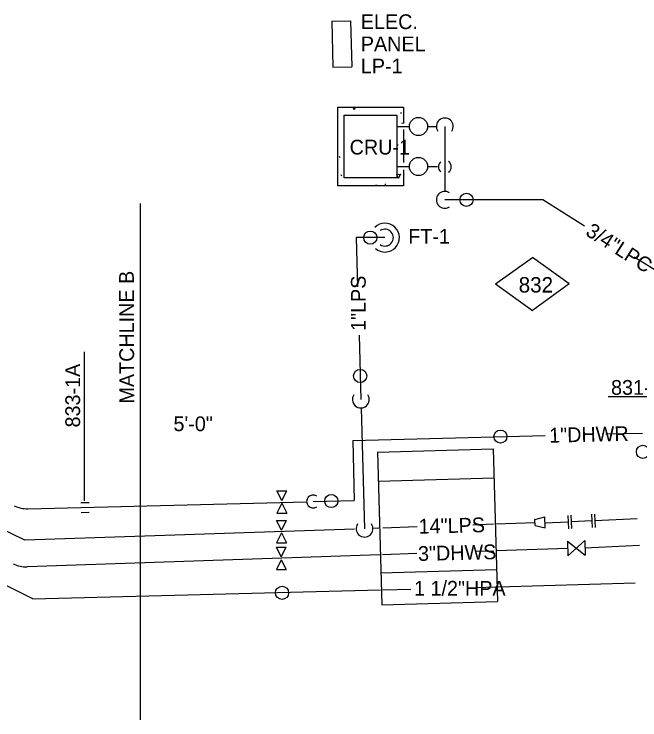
# Model space of a CAD drawing. Extents: x 9888 to 10178, y 10284 to 10314.
# Drawn here: x 9928.84 to 9944.72, y 10285.52 to 10303.43 of the extents above; entities that cross this region are included whole.
import ezdxf

# ---------------------------------------------------------------- set-up
doc = ezdxf.new("R2010")
doc.units = 0
for name, color, linetype in [('Level 51', 7, 'Continuous'), ('Level 52', 7, 'Continuous'), ('Level 55', 7, 'Continuous'), ('Level 62', 7, 'Continuous'), ('M-ANNO-NPLT', 7, 'Continuous'), ('M-EQPM-N', 7, 'Continuous'), ('M-HVAC-SUPP-N', 7, 'Continuous'), ('M-PROC-PIPE', 7, 'Continuous'), ('M-STEM-CONP', 7, 'Continuous'), ('M-STEM-CONP-N', 7, 'Continuous'), ('P-CMPA-PIPE', 7, 'Continuous'), ('P-DOMW-HPIP', 7, 'Continuous'), ('P-DOMW-HPIP-N', 7, 'Continuous')]:
    doc.layers.add(name, color=color, linetype=linetype)

msp = doc.modelspace()

# ---------------------------------------------------------------- linework, layer by layer
at = {"layer": 'Level 51'}
for p, q in [((9938.669, 10300.9), (9938.656, 10300.934)), ((9938.556, 10300.581), (9938.869, 10300.581)), ((9938.666, 10300.673), (9938.692, 10300.668)), ((9939.331, 10300.581), (9939.547, 10300.581)), ((9939.768, 10300.581), (9939.768, 10298.937)), ((9937.113, 10299.788), (9937.1, 10299.822)), ((9938.556, 10299.564), (9938.869, 10299.564)), ((9939.331, 10299.564), (9939.586, 10299.564)), ((9937.155, 10299.322), (9937.142, 10299.356)), ((9938.245, 10299.126), (9938.271, 10299.105)), ((9942.258, 10298.719), (9939.768, 10298.719)), ((9943.318, 10298.054), (9942.258, 10298.719)), ((9938.249, 10297.759), (9937.521, 10297.759)), ((9937.521, 10297.759), (9937.556, 10296.514)), ((9941.058, 10296.583), (9941.991, 10297.255)), ((9942.924, 10296.583), (9941.991, 10297.255)), ((9945.996, 10296.374), (9944.576, 10297.265)), ((9941.058, 10296.583), (9941.991, 10295.911)), ((9942.924, 10296.583), (9941.991, 10295.911)), ((9937.592, 10295.279), (9937.638, 10293.651)), ((9937.644, 10293.437), (9937.732, 10290.37)), ((9938.058, 10292.312), (9940.999, 10292.396)), ((9938.058, 10292.312), (9938.169, 10288.439)), ((9940.999, 10292.396), (9941.11, 10288.523)), ((9938.079, 10291.573), (9941.02, 10291.657)), ((9938.146, 10289.246), (9941.087, 10289.33)), ((9938.169, 10288.439), (9941.11, 10288.523))]:
    msp.add_line(p, q, dxfattribs=at)
for points in [[(9938.721, 10299.48), (9938.721, 10299.072), (9937.054, 10299.072), (9937.054, 10301.072), (9938.721, 10301.072), (9938.721, 10300.656)], [(9937.469, 10301.004), (9937.445, 10301.072)], [(9937.504, 10301.072), (9937.469, 10301.004)], [(9938.721, 10300.506), (9938.721, 10299.663)], [(9938.549, 10300.119), (9938.574, 10300.123), (9938.549, 10300.075)], [(9938.585, 10299.263), (9938.551, 10299.359), (9938.643, 10299.372), (9938.585, 10299.263)], [(9938.026, 10299.072), (9938.01, 10299.093), (9938.05, 10299.092)]]:
    msp.add_lwpolyline(points, dxfattribs=at)
msp.add_lwpolyline([(9937.215, 10299.28), (9937.215, 10300.864), (9938.549, 10300.864), (9938.549, 10299.28)], close=True, dxfattribs=at)
for centre, radius in [((9939.1, 10300.581), 0.231), ((9939.1, 10299.564), 0.231), ((9940.32, 10298.719), 0.167), ((9937.878, 10297.759), 0.167), ((9937.621, 10294.247), 0.167)]:
    msp.add_circle(centre, radius, dxfattribs=at)
for centre, radius, start, end in [((9939.768, 10300.581), 0.214, 326.0383, 213.8362), ((9939.769, 10299.555), 0.164, 127.3529, 230.1974), ((9939.769, 10299.555), 0.164, 304.8908, 55.1092), ((9939.768, 10298.719), 0.214, 56.0383, 303.8362), ((9938.249, 10297.759), 0.366, 228.3299, 134.4653), ((9938.249, 10297.759), 0.214, 236.0383, 123.8362), ((9937.638, 10293.651), 0.214, 146.0383, 33.8362), ((9937.732, 10290.37), 0.214, 146.0383, 33.8362)]:
    msp.add_arc(centre, radius, start, end, dxfattribs=at)
at = {"layer": 'Level 55'}
for centre in [(9941.18, 10292.708), (9944.798, 10292.32), (9936.888, 10291.072)]:
    msp.add_circle(centre, 0.167, dxfattribs=at)
at = {"layer": 'Level 62'}
for p, q in [((9936.902, 10303.254), (9937.378, 10303.265)), ((9936.902, 10303.254), (9936.928, 10302.088)), ((9937.378, 10303.265), (9937.405, 10302.098)), ((9936.928, 10302.088), (9937.405, 10302.098))]:
    msp.add_line(p, q, dxfattribs=at)
at = {"layer": 'M-ANNO-NPLT'}
msp.add_line((9930.627, 10291.078), (9930.627, 10294.861), dxfattribs=at)
at = {"layer": 'M-EQPM-N'}
msp.add_line((9945.961, 10293.714), (9943.913, 10293.714), dxfattribs=at)
at = {"layer": 'M-PROC-PIPE'}
for p, q in [((9937.433, 10292.612), (9942.315, 10292.737)), ((9943.856, 10292.776), (9944.79, 10292.799)), ((9937.433, 10292.612), (9937.471, 10291.086)), ((9935.631, 10291.084), (9935.507, 10291.332)), ((9935.507, 10291.332), (9935.755, 10291.332)), ((9935.631, 10291.084), (9935.755, 10291.332)), ((9929.186, 10290.876), (9936.261, 10291.056)), ((9936.425, 10291.06), (9937.471, 10291.086)), ((9930.534, 10291.033), (9930.738, 10291.038)), ((9935.631, 10291.015), (9935.507, 10290.767)), ((9935.631, 10291.015), (9935.755, 10290.767)), ((9930.54, 10290.783), (9930.744, 10290.788)), ((9935.507, 10290.767), (9935.755, 10290.767))]:
    msp.add_line(p, q, dxfattribs=at)
for centre, radius, start, end in [((9936.425, 10291.06), 0.164, 56.0383, 303.8362), ((9929.167, 10291.626), 0.75, 243.8756, 271.4564)]:
    msp.add_arc(centre, radius, start, end, dxfattribs=at)
at = {"layer": 'M-STEM-CONP'}
for p, q in [((9932.043, 10285.516), (9932.043, 10298.625)), ((9929.106, 10290.078), (9915.239, 10296.879)), ((9935.625, 10290.331), (9935.501, 10290.579)), ((9935.501, 10290.579), (9935.748, 10290.579)), ((9935.625, 10290.331), (9935.748, 10290.579)), ((9942.059, 10290.517), (9941.063, 10290.483)), ((9942.057, 10290.6), (9942.308, 10290.671)), ((9942.061, 10290.449), (9942.057, 10290.6)), ((9942.314, 10290.391), (9942.308, 10290.671)), ((9942.899, 10290.538), (9942.311, 10290.51)), ((9944.649, 10290.621), (9943.577, 10290.57)), ((9937.48, 10290.362), (9929.106, 10290.078)), ((9938.096, 10290.383), (9937.971, 10290.378)), ((9939.068, 10290.416), (9938.195, 10290.386)), ((9941.003, 10290.481), (9940.476, 10290.463)), ((9942.061, 10290.449), (9942.314, 10290.391)), ((9935.625, 10290.261), (9935.501, 10290.014)), ((9935.625, 10290.261), (9935.748, 10290.014)), ((9935.501, 10290.014), (9935.748, 10290.014))]:
    msp.add_line(p, q, dxfattribs=at)
at = {"layer": 'M-STEM-CONP-N'}
for p, q in [((9942.891, 10290.707), (9942.907, 10290.369)), ((9942.97, 10290.711), (9942.986, 10290.373)), ((9943.491, 10290.735), (9943.507, 10290.398)), ((9943.569, 10290.739), (9943.585, 10290.401)), ((9943.499, 10290.566), (9942.978, 10290.542))]:
    msp.add_line(p, q, dxfattribs=at)
at = {"layer": 'P-CMPA-PIPE'}
for p, q in [((9929.314, 10288.592), (9913.444, 10296.374)), ((9941.122, 10288.893), (9944.6, 10288.993)), ((9929.314, 10288.592), (9938.135, 10288.816)), ((9938.195, 10288.817), (9938.905, 10288.835)), ((9940.575, 10288.878), (9941.052, 10288.891))]:
    msp.add_line(p, q, dxfattribs=at)
msp.add_circle((9935.637, 10288.743), 0.167, dxfattribs=at)
at = {"layer": 'P-DOMW-HPIP-N'}
for p, q in [((9942.882, 10290.057), (9942.894, 10289.682)), ((9942.882, 10290.057), (9943.331, 10289.696)), ((9943.319, 10290.071), (9942.894, 10289.682)), ((9943.319, 10290.071), (9943.331, 10289.696)), ((9935.618, 10289.652), (9935.494, 10289.899)), ((9935.494, 10289.899), (9935.742, 10289.899)), ((9935.618, 10289.652), (9935.742, 10289.899)), ((9941.013, 10289.803), (9940.556, 10289.787)), ((9942.888, 10289.866), (9941.073, 10289.805)), ((9944.709, 10289.945), (9943.325, 10289.879)), ((9938.116, 10289.705), (9929.17, 10289.402)), ((9939.058, 10289.737), (9938.185, 10289.707)), ((9935.618, 10289.582), (9935.494, 10289.334)), ((9935.618, 10289.582), (9935.742, 10289.334)), ((9935.494, 10289.334), (9935.742, 10289.334))]:
    msp.add_line(p, q, dxfattribs=at)
msp.add_arc((9929.145, 10290.152), 0.75, 243.8756, 271.9385, dxfattribs=at)

# ---------------------------------------------------------------- texts
at = {"layer": 'Level 51'}
for s, height, p in [('CRU-1', 0.375, (9937.353, 10299.869)), ('FT-1', 0.375, (9938.84, 10297.604)), ('832', 0.3915, (9941.644, 10296.366))]:
    msp.add_text(s, height=height, dxfattribs=at).set_placement(p)
at = {"layer": 'Level 52'}
for s, rotation, p in [('3/4"LPC', 327.4964, (9943.316, 10297.839)), ('1"LPS', 90, (9937.761, 10295.39))]:
    msp.add_text(s, height=0.375, rotation=rotation, dxfattribs=at).set_placement(p)
at = {"layer": 'Level 55'}
msp.add_text('1"DHWR', height=0.375, rotation=1.3556, dxfattribs=at).set_placement((9942.422, 10292.553))
at = {"layer": 'Level 62'}
for s, p in [('ELEC.', (9937.637, 10303.053)), ('PANEL', (9937.637, 10302.49)), ('LP-1', (9937.637, 10301.928))]:
    msp.add_text(s, height=0.375, dxfattribs=at).set_placement(p)
at = {"layer": 'M-ANNO-NPLT'}
msp.add_text('MATCHLINE B', height=0.375, rotation=90.1595, dxfattribs=at).set_placement((9931.885, 10293.547))
at = {"layer": 'M-EQPM-N'}
for s, p in [('831-14', (9943.988, 10293.769)), ('5\'-0"', (9932.882, 10292.846))]:
    msp.add_text(s, height=0.375, dxfattribs=at).set_placement(p)
at = {"layer": 'M-HVAC-SUPP-N'}
msp.add_text('833-1A', height=0.375, rotation=90, dxfattribs=at).set_placement((9930.512, 10292.94))
at = {"layer": 'M-STEM-CONP'}
msp.add_text('14"LPS', height=0.375, rotation=1.3556, dxfattribs=at).set_placement((9939.108, 10290.243))
at = {"layer": 'P-CMPA-PIPE'}
msp.add_text('1 1/2"HPA', height=0.375, dxfattribs=at).set_placement((9938.988, 10288.669))
at = {"layer": 'P-DOMW-HPIP'}
msp.add_text('3"DHWS', height=0.375, rotation=1.3556, dxfattribs=at).set_placement((9939.093, 10289.55))

doc.saveas('drawing.dxf')
